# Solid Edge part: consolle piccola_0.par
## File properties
Last saved by: i.fialdini
Revision: 62
Tipo di contenuto documento: 0
Accuracy: 0.990
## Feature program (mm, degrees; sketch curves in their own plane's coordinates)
body "unnamed Body 1"
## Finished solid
Body 1: solid body, 4 faces, 4 edges, 0 vertices.
  Faces by surface: cylinder 2, plane 2
  Edges by curve: circle 4
Bounding box of the edges (mm): 18.950 x 18.950 x 53.817, from (194.0767, -896.6832, 648.6083) to (213.0264, -877.7335, 702.4253).
Cylindrical faces by radius (mm): R7 x1, R8.5 x1
Planar faces by outward normal: oblique 2
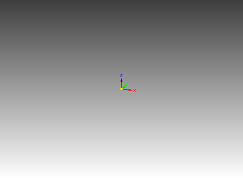
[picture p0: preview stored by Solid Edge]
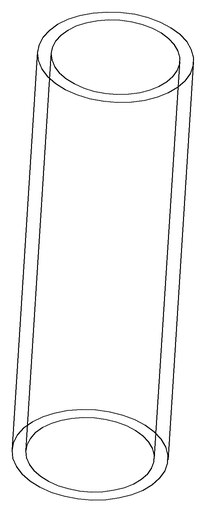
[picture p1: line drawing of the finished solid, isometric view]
